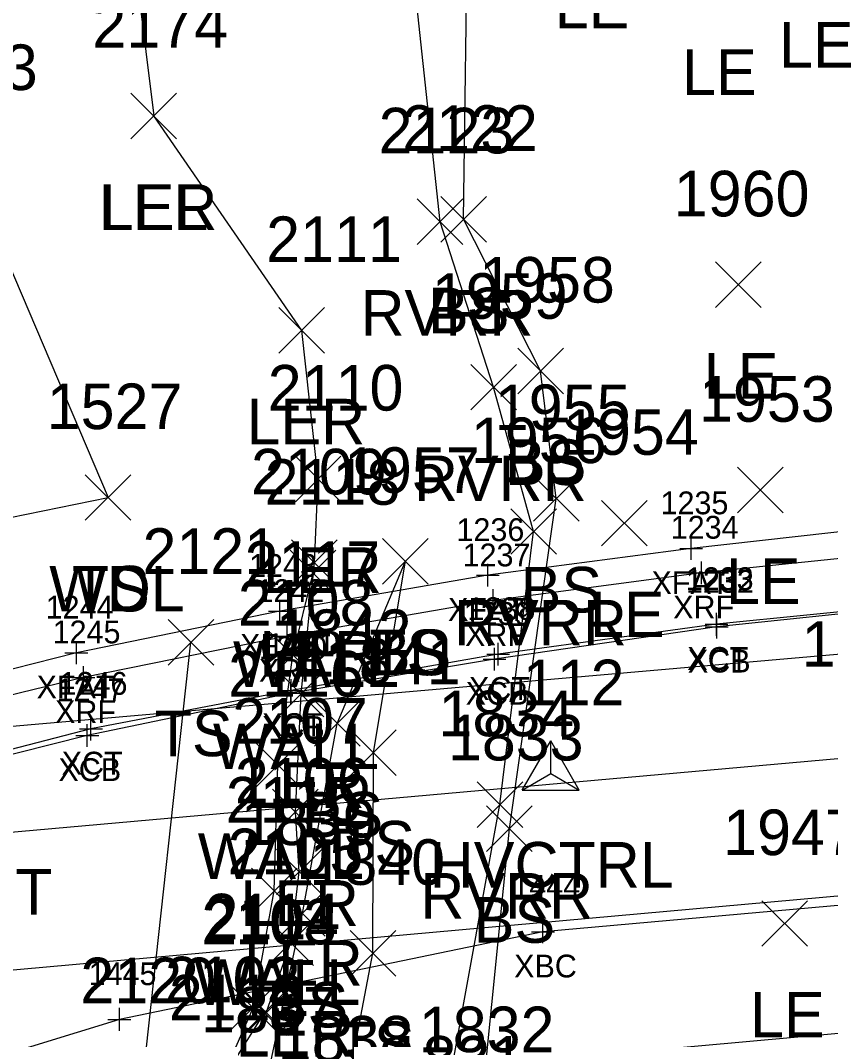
# Model space of a CAD drawing. Extents: x 1638344 to 1639591, y 610835 to 612202.
# Drawn here: x 1638651.32 to 1638686.84, y 611696.6 to 611741.32 of the extents above; entities that cross this region are included whole.
import ezdxf

# ---------------------------------------------------------------- set-up
doc = ezdxf.new("R2010")
doc.units = 0
for name, color, linetype in [('B_A', 7, 'Continuous'), ('B_I', 7, 'Continuous'), ('B_TIC', 7, 'Continuous'), ('BB', 7, 'Continuous'), ('BDC', 7, 'Continuous'), ('BELB', 7, 'Continuous'), ('BF', 7, 'Continuous'), ('BR', 7, 'Continuous'), ('C_A', 7, 'Continuous'), ('C_I', 7, 'Continuous'), ('CPSM', 7, 'Continuous'), ('L_A', 7, 'Continuous'), ('L_I', 7, 'Continuous'), ('L_TIC', 7, 'Continuous'), ('LARO', 7, 'Continuous'), ('LAWA', 7, 'Continuous'), ('LAWE', 7, 'Continuous'), ('LELB', 7, 'Continuous'), ('LW', 7, 'Continuous'), ('R_C', 7, 'Continuous')]:
    doc.layers.add(name, color=color, linetype=linetype)

msp = doc.modelspace()

# ---------------------------------------------------------------- linework, layer by layer
at = {"layer": 'B_TIC'}
for p, q in [((1638680.737, 611718.15), (1638680.813, 611718.15)), ((1638671.818, 611716.974), (1638671.893, 611716.974)), ((1638681.184, 611717.08), (1638681.26, 611717.08)), ((1638672.058, 611715.864), (1638672.133, 611715.864)), ((1638662.698, 611715.401), (1638662.773, 611715.401)), ((1638681.842, 611714.822), (1638681.918, 611714.822)), ((1638663.021, 611714.299), (1638663.096, 611714.299)), ((1638681.854, 611714.706), (1638681.93, 611714.706)), ((1638653.777, 611713.573), (1638653.853, 611713.573)), ((1638672.27, 611713.507), (1638672.345, 611713.507)), ((1638672.111, 611713.295), (1638672.187, 611713.295)), ((1638654.083, 611712.487), (1638654.159, 611712.487)), ((1638663.182, 611711.795), (1638663.257, 611711.795)), ((1638663.199, 611711.921), (1638663.275, 611711.921)), ((1638654.256, 611709.944), (1638654.331, 611709.944)), ((1638654.417, 611710.23), (1638654.493, 611710.23)), ((1638674.236, 611701.328), (1638674.312, 611701.328)), ((1638655.662, 611697.489), (1638655.737, 611697.489))]:
    msp.add_line(p, q, dxfattribs=at)
for points in [[(1638680.734, 611717.65), (1638680.734, 611718.65)], [(1638680.234, 611718.15), (1638681.234, 611718.15)], [(1638671.814, 611716.474), (1638671.814, 611717.474)], [(1638681.181, 611716.58), (1638681.181, 611717.58)], [(1638671.314, 611716.974), (1638672.314, 611716.974)], [(1638680.681, 611717.08), (1638681.681, 611717.08)], [(1638672.054, 611715.364), (1638672.054, 611716.364)], [(1638662.694, 611714.901), (1638662.694, 611715.901)], [(1638671.554, 611715.864), (1638672.554, 611715.864)], [(1638662.194, 611715.401), (1638663.194, 611715.401)], [(1638681.839, 611714.322), (1638681.839, 611715.322)], [(1638681.851, 611714.206), (1638681.851, 611715.206)], [(1638663.017, 611713.799), (1638663.017, 611714.799)], [(1638681.339, 611714.822), (1638682.339, 611714.822)], [(1638662.517, 611714.299), (1638663.517, 611714.299)], [(1638681.351, 611714.706), (1638682.351, 611714.706)], [(1638653.774, 611713.073), (1638653.774, 611714.073)], [(1638672.266, 611713.007), (1638672.266, 611714.007)], [(1638653.274, 611713.573), (1638654.274, 611713.573)], [(1638671.766, 611713.507), (1638672.766, 611713.507)], [(1638672.108, 611712.795), (1638672.108, 611713.795)], [(1638654.08, 611711.987), (1638654.08, 611712.987)], [(1638671.608, 611713.295), (1638672.608, 611713.295)], [(1638653.58, 611712.487), (1638654.58, 611712.487)], [(1638663.178, 611711.295), (1638663.178, 611712.295)], [(1638663.196, 611711.421), (1638663.196, 611712.421)], [(1638662.678, 611711.795), (1638663.678, 611711.795)], [(1638662.696, 611711.921), (1638663.696, 611711.921)], [(1638654.414, 611709.73), (1638654.414, 611710.73)], [(1638654.252, 611709.444), (1638654.252, 611710.444)], [(1638653.752, 611709.944), (1638654.752, 611709.944)], [(1638653.914, 611710.23), (1638654.914, 611710.23)], [(1638674.233, 611700.828), (1638674.233, 611701.828)], [(1638673.733, 611701.328), (1638674.733, 611701.328)], [(1638655.658, 611696.989), (1638655.658, 611697.989)], [(1638655.158, 611697.489), (1638656.158, 611697.489)]]:
    msp.add_lwpolyline(points, dxfattribs=at)
at = {"layer": 'BB'}
for points in [[(1638734.87, 611717.669), (1638645.425, 611709.859)], [(1638734.903, 611713.182), (1638645.469, 611705.203)], [(1638735.197, 611707.211), (1638645.609, 611699.159)], [(1638735.113, 611701.19), (1638645.728, 611693.119)]]:
    msp.add_lwpolyline(points, dxfattribs=at)
at = {"layer": 'BDC'}
for points in [[(1638737.305, 611718.795), (1638737.221, 611715.93), (1638737.034, 611715.608), (1638736.539, 611715.364), (1638735.749, 611715.325), (1638725.935, 611715.986), (1638717.241, 611716.45), (1638708.031, 611716.471), (1638699.246, 611716.24), (1638689.973, 611715.561), (1638681.851, 611714.706), (1638672.108, 611713.295), (1638663.178, 611711.795), (1638654.252, 611709.944), (1638645.027, 611707.62), (1638643.746, 611707.614), (1638643.485, 611708.194), (1638643.486, 611710.833)], [(1638737.078, 611718.736), (1638737.03, 611716.376), (1638736.823, 611715.856), (1638736.034, 611715.473), (1638725.908, 611716.152), (1638717.252, 611716.548), (1638708.082, 611716.671), (1638699.284, 611716.36), (1638690.06, 611715.643), (1638681.839, 611714.822), (1638672.266, 611713.507), (1638663.196, 611711.921), (1638654.414, 611710.23), (1638644.982, 611707.789), (1638643.919, 611707.854), (1638643.654, 611708.237), (1638643.636, 611710.999)]]:
    msp.add_lwpolyline(points, dxfattribs=at)
at = {"layer": 'BELB'}
msp.add_lwpolyline([(1638736.563, 611702.566), (1638717.385, 611703.723), (1638696.176, 611703.285), (1638674.233, 611701.328), (1638655.658, 611697.489), (1638644.13, 611693.949)], dxfattribs=at)
at = {"layer": 'BF'}
msp.add_lwpolyline([(1638737.078, 611718.736), (1638726.453, 611719.594), (1638717.231, 611720.061), (1638708.125, 611720.112), (1638698.897, 611719.862), (1638689.982, 611719.193), (1638680.734, 611718.15), (1638671.814, 611716.974), (1638662.694, 611715.401), (1638653.774, 611713.573), (1638643.636, 611710.999)], dxfattribs=at)
at = {"layer": 'BR'}
msp.add_lwpolyline([(1638736.42, 611718.625), (1638736.346, 611717.75), (1638726.195, 611718.354), (1638717.373, 611718.813), (1638708.189, 611718.979), (1638699.169, 611718.709), (1638690.094, 611717.999), (1638681.181, 611717.08), (1638672.054, 611715.864), (1638663.017, 611714.299), (1638654.08, 611712.487), (1638644.592, 611710.18), (1638644.314, 611711.068)], dxfattribs=at)
at = {"layer": 'CPSM'}
for p, q in [((1638673.324, 611707.548), (1638674.574, 611709.713)), ((1638675.824, 611707.548), (1638674.574, 611709.713)), ((1638674.575, 611708.27), (1638674.574, 611709.713)), ((1638673.324, 611707.548), (1638674.575, 611708.27)), ((1638674.575, 611708.27), (1638674.575, 611708.27)), ((1638674.575, 611708.27), (1638675.824, 611707.548)), ((1638673.324, 611707.548), (1638675.824, 611707.548))]:
    msp.add_line(p, q, dxfattribs=at)
at = {"layer": 'L_TIC'}
for points in [[(1638656.167, 611736.126), (1638658.167, 611738.126)], [(1638658.167, 611736.126), (1638656.167, 611738.126)], [(1638656.167, 611736.126), (1638658.167, 611738.126)], [(1638658.167, 611736.126), (1638656.167, 611738.126)], [(1638669.752, 611731.595), (1638671.752, 611733.595)], [(1638671.752, 611731.595), (1638669.752, 611733.595)], [(1638668.72, 611731.484), (1638670.72, 611733.484)], [(1638670.72, 611731.484), (1638668.72, 611733.484)], [(1638681.795, 611728.72), (1638683.795, 611730.72)], [(1638683.795, 611728.72), (1638681.795, 611730.72)], [(1638662.653, 611726.717), (1638664.653, 611728.717)], [(1638664.653, 611726.717), (1638662.653, 611728.717)], [(1638673.129, 611724.937), (1638675.129, 611726.937)], [(1638675.129, 611724.937), (1638673.129, 611726.937)], [(1638671.065, 611724.227), (1638673.065, 611726.227)], [(1638673.065, 611724.227), (1638671.065, 611726.227)], [(1638663.377, 611720.2), (1638665.377, 611722.2)], [(1638665.377, 611720.2), (1638663.377, 611722.2)], [(1638682.768, 611719.71), (1638684.768, 611721.71)], [(1638684.768, 611719.71), (1638682.768, 611721.71)], [(1638654.164, 611719.387), (1638656.164, 611721.387)], [(1638656.164, 611719.387), (1638654.164, 611721.387)], [(1638654.164, 611719.387), (1638656.164, 611721.387)], [(1638656.164, 611719.387), (1638654.164, 611721.387)], [(1638673.815, 611719.343), (1638675.815, 611721.343)], [(1638675.815, 611719.343), (1638673.815, 611721.343)], [(1638676.805, 611718.259), (1638678.805, 611720.259)], [(1638678.805, 611718.259), (1638676.805, 611720.259)], [(1638672.822, 611717.895), (1638674.822, 611719.895)], [(1638674.822, 611717.895), (1638672.822, 611719.895)], [(1638663.209, 611716.521), (1638665.209, 611718.521)], [(1638665.209, 611716.521), (1638663.209, 611718.521)], [(1638667.203, 611716.588), (1638669.203, 611718.588)], [(1638669.203, 611716.588), (1638667.203, 611718.588)], [(1638667.203, 611716.588), (1638669.203, 611718.588)], [(1638669.203, 611716.588), (1638667.203, 611718.588)], [(1638663.155, 611716.068), (1638665.155, 611718.068)], [(1638665.155, 611716.068), (1638663.155, 611718.068)], [(1638657.799, 611713.035), (1638659.799, 611715.035)], [(1638659.799, 611713.035), (1638657.799, 611715.035)], [(1638662.272, 611712.469), (1638664.272, 611714.469)], [(1638664.272, 611712.469), (1638662.272, 611714.469)], [(1638662.624, 611710.768), (1638664.624, 611712.768)], [(1638664.624, 611710.768), (1638662.624, 611712.768)], [(1638664.216, 611709.473), (1638666.216, 611711.473)], [(1638666.216, 611709.473), (1638664.216, 611711.473)], [(1638665.797, 611708.194), (1638667.797, 611710.194)], [(1638667.797, 611708.194), (1638665.797, 611710.194)], [(1638661.609, 611707.652), (1638663.609, 611709.652)], [(1638663.609, 611707.652), (1638661.609, 611709.652)], [(1638662.377, 611705.584), (1638664.377, 611707.584)], [(1638664.377, 611705.584), (1638662.377, 611707.584)], [(1638671.343, 611705.91), (1638673.343, 611707.91)], [(1638673.343, 611705.91), (1638671.343, 611707.91)], [(1638671.758, 611704.85), (1638673.758, 611706.85)], [(1638673.758, 611704.85), (1638671.758, 611706.85)], [(1638662.547, 611702.961), (1638664.547, 611704.961)], [(1638664.547, 611702.961), (1638662.547, 611704.961)], [(1638661.45, 611702.124), (1638663.45, 611704.124)], [(1638663.45, 611702.124), (1638661.45, 611704.124)], [(1638662.689, 611701.135), (1638664.689, 611703.135)], [(1638664.689, 611701.135), (1638662.689, 611703.135)], [(1638683.827, 611700.695), (1638685.827, 611702.695)], [(1638685.827, 611700.695), (1638683.827, 611702.695)], [(1638662.175, 611699.857), (1638664.175, 611701.857)], [(1638664.175, 611699.857), (1638662.175, 611701.857)], [(1638665.775, 611699.389), (1638667.775, 611701.389)], [(1638667.775, 611699.389), (1638665.775, 611701.389)], [(1638660.52, 611696.998), (1638662.52, 611698.998)], [(1638662.52, 611696.998), (1638660.52, 611698.998)], [(1638661.023, 611696.78), (1638663.023, 611698.78)], [(1638663.023, 611696.78), (1638661.023, 611698.78)], [(1638661.102, 611696.781), (1638663.102, 611698.781)], [(1638663.102, 611696.781), (1638661.102, 611698.781)]]:
    msp.add_lwpolyline(points, dxfattribs=at)
at = {"layer": 'LARO'}
for points in [[(1638668.019, 611809.745), (1638662.223, 611800.014), (1638655.604, 611791.826), (1638656.981, 611771.118), (1638658.475, 611759.642), (1638655.748, 611748.56), (1638657.167, 611737.126)], [(1638677.874, 611655.022), (1638679.486, 611663.994), (1638679.763, 611666.345), (1638666.378, 611670.719), (1638664.402, 611680.56), (1638659.089, 611680.603), (1638655.538, 611679.933), (1638651.379, 611684.077), (1638658.688, 611689.813), (1638660.426, 611695.236), (1638662.023, 611697.78), (1638662.102, 611697.781), (1638663.175, 611700.857), (1638663.547, 611703.961), (1638663.377, 611706.584), (1638663.624, 611711.768), (1638664.209, 611717.521), (1638664.377, 611721.2), (1638663.653, 611727.717), (1638657.167, 611737.126)]]:
    msp.add_lwpolyline(points, dxfattribs=at)
at = {"layer": 'LAWA'}
msp.add_lwpolyline([(1638628.579, 611823.011), (1638631.205, 611793.982), (1638636.051, 611775.752), (1638635.636, 611758.892), (1638640.82, 611743.59), (1638643.87, 611738.789), (1638644.553, 611728.051), (1638647.989, 611718.924), (1638655.164, 611720.387)], dxfattribs=at)
at = {"layer": 'LAWE'}
msp.add_lwpolyline([(1638639.67, 611638.455), (1638651.909, 611645.684), (1638665.496, 611649.056), (1638676.655, 611655.904), (1638679.763, 611666.345), (1638680.738, 611673.208), (1638671.065, 611682.751), (1638669.589, 611691.757), (1638672.343, 611706.91), (1638673.822, 611718.895), (1638672.065, 611725.227), (1638669.72, 611732.484), (1638668.237, 611746.392), (1638671.195, 611757.256), (1638673.317, 611772.941), (1638670.756, 611783.04), (1638669.117, 611796.001), (1638668.019, 611809.745), (1638668.561, 611829.322)], dxfattribs=at)
at = {"layer": 'LELB'}
for points in [[(1638679.486, 611663.994), (1638681.736, 611674.726), (1638674.098, 611683.416), (1638671.48, 611693.048), (1638672.758, 611705.85), (1638674.815, 611720.343), (1638674.129, 611725.937), (1638670.752, 611732.595), (1638670.942, 611746.441), (1638675.273, 611751.303), (1638676.509, 611756.644), (1638676.731, 611772.908), (1638673.469, 611784.839), (1638671, 611795.643), (1638672.782, 611808.122), (1638670.59, 611829.25)], [(1638643.87, 611738.789), (1638648.823, 611735.263), (1638655.164, 611720.387)], [(1638665.17, 611684.637), (1638658.464, 611683.85), (1638661.932, 611693.915), (1638663.689, 611702.135), (1638665.216, 611710.473), (1638668.203, 611717.588)], [(1638665.17, 611684.637), (1638665.296, 611692.638), (1638666.775, 611700.389), (1638666.797, 611709.194), (1638668.203, 611717.588)], [(1638653.675, 611690.062), (1638656.73, 611695.195), (1638658.799, 611714.035)]]:
    msp.add_lwpolyline(points, dxfattribs=at)
at = {"layer": 'LW'}
msp.add_lwpolyline([(1638658.718, 611691.07), (1638659.956, 611694.444), (1638661.52, 611697.998), (1638662.45, 611703.124), (1638662.609, 611708.652), (1638663.272, 611713.469), (1638664.155, 611717.068)], dxfattribs=at)

# ---------------------------------------------------------------- texts
at = {"layer": 'B_A'}
for s, p in [('XFAT', (1638678.99, 611716.15)), ('XRF', (1638679.941, 611715.08)), ('XFAT', (1638670.07, 611714.974)), ('XRF', (1638670.814, 611713.864)), ('XFAT', (1638660.95, 611713.401)), ('XCT', (1638680.559, 611712.822)), ('XCB', (1638680.587, 611712.706)), ('XRF', (1638661.777, 611712.299)), ('XFAT', (1638652.03, 611711.573)), ('XCT', (1638670.987, 611711.507)), ('XCB', (1638670.844, 611711.295)), ('XRF', (1638652.84, 611710.487)), ('XCB', (1638661.915, 611709.795)), ('XCT', (1638661.916, 611709.921)), ('XCB', (1638652.988, 611707.944)), ('XCT', (1638653.134, 611708.23)), ('XBC', (1638672.969, 611699.328))]:
    msp.add_text(s, height=1, dxfattribs=at).set_placement(p)
at = {"layer": 'B_I'}
for s, p in [('1235', (1638679.388, 611719.65)), ('1236', (1638670.44, 611718.474)), ('1234', (1638679.834, 611718.58)), ('1237', (1638670.708, 611717.364)), ('1243', (1638661.348, 611716.901)), ('1233', (1638680.492, 611716.322)), ('1232', (1638680.504, 611716.206)), ('1242', (1638661.671, 611715.799)), ('1244', (1638652.427, 611715.073)), ('1239', (1638670.758, 611714.795)), ('1238', (1638670.92, 611715.007)), ('1245', (1638652.733, 611713.987)), ('1240', (1638661.789, 611713.295)), ('1241', (1638662.133, 611713.421)), ('1246', (1638653.04, 611711.73)), ('1247', (1638652.906, 611711.444)), ('1444', (1638672.886, 611702.828)), ('1445', (1638654.312, 611698.989))]:
    msp.add_text(s, height=1, dxfattribs=at).set_placement(p)
at = {"layer": 'C_A'}
msp.add_text('HVCTRL', height=2, dxfattribs=at).set_placement((1638669.268, 611703.27))
at = {"layer": 'C_I'}
msp.add_text('112', height=2, dxfattribs=at).set_placement((1638673.346, 611711.27))
at = {"layer": 'L_A'}
for s, p in [('LE', (1638674.751, 611740.967)), ('LE', (1638684.579, 611739.247)), ('LE', (1638680.332, 611738.045)), ('LER', (1638654.75, 611732.126)), ('LEL', (1638654.805, 611732.126)), ('RVRR', (1638666.232, 611727.484)), ('BS', (1638669.192, 611727.595)), ('LE', (1638681.283, 611724.72)), ('LER', (1638661.236, 611722.717)), ('BS', (1638672.57, 611720.937)), ('RVRR', (1638668.577, 611720.227)), ('LER', (1638661.96, 611716.2)), ('TS', (1638653.574, 611715.387)), ('LE', (1638682.256, 611715.71)), ('WDL', (1638652.582, 611715.387)), ('BS', (1638673.256, 611715.343)), ('LE', (1638676.293, 611714.259)), ('RVRR', (1638670.334, 611713.895)), ('LER', (1638661.792, 611712.521)), ('TS', (1638666.613, 611712.588)), ('BS', (1638666.644, 611712.588)), ('WALL', (1638660.643, 611712.068)), ('TS', (1638657.209, 611709.035)), ('WALL', (1638659.76, 611708.469)), ('LER', (1638661.207, 611706.768)), ('BS', (1638663.657, 611705.473)), ('TS', (1638665.206, 611704.194)), ('WALL', (1638659.097, 611703.652)), ('LER', (1638660.96, 611701.584)), ('RVRR', (1638668.855, 611701.91)), ('BS', (1638671.199, 611700.85)), ('LER', (1638661.13, 611698.961)), ('WALL', (1638658.938, 611698.124)), ('BS', (1638662.13, 611697.135)), ('LE', (1638683.315, 611696.695)), ('LER', (1638660.758, 611695.857)), ('TS', (1638665.184, 611695.389))]:
    msp.add_text(s, height=2, dxfattribs=at).set_placement(p)
at = {"layer": 'L_I'}
for s, p in [('2174', (1638654.474, 611740.126)), ('2174', (1638654.474, 611740.126)), ('1523', (1638646.13, 611738.263)), ('2122', (1638668.059, 611735.595)), ('2123', (1638667.027, 611735.484)), ('1960', (1638679.968, 611732.72)), ('2111', (1638662.094, 611730.717)), ('1958', (1638671.436, 611728.937)), ('1959', (1638669.365, 611728.227)), ('2110', (1638662.165, 611724.2)), ('1953', (1638681.075, 611723.71)), ('1527', (1638652.471, 611723.387)), ('1527', (1638652.471, 611723.387)), ('1955', (1638672.122, 611723.343)), ('1954', (1638675.112, 611722.259)), ('1956', (1638671.074, 611721.895)), ('2109', (1638661.43, 611720.521)), ('1957', (1638665.51, 611720.588)), ('1957', (1638665.51, 611720.588)), ('2118', (1638662.029, 611720.068)), ('2121', (1638656.673, 611717.035)), ('2117', (1638661.146, 611716.469)), ('2108', (1638660.853, 611714.768)), ('1842', (1638662.523, 611713.473)), ('1948', (1638685.571, 611712.958)), ('1841', (1638664.671, 611712.194)), ('2116', (1638660.427, 611711.652)), ('2107', (1638660.606, 611709.584)), ('1834', (1638669.65, 611709.91)), ('1833', (1638670.065, 611708.85)), ('2106', (1638660.721, 611706.961)), ('2115', (1638660.324, 611706.124)), ('1839', (1638660.988, 611705.135)), ('1947', (1638682.134, 611704.695)), ('2105', (1638660.404, 611703.857)), ('1840', (1638663.995, 611703.389)), ('2103', (1638659.252, 611700.78)), ('2104', (1638659.331, 611700.781)), ('2114', (1638659.394, 611700.998)), ('2120', (1638653.95, 611698.195)), ('2102', (1638657.654, 611698.236)), ('2113', (1638657.83, 611697.444)), ('1837', (1638659.239, 611696.915)), ('1832', (1638668.787, 611696.048)), ('1838', (1638662.603, 611695.638)), ('1831', (1638667.464, 611694.757))]:
    msp.add_text(s, height=2, dxfattribs=at).set_placement(p)
at = {"layer": 'R_C'}
msp.add_text('SGR STEEL POST', height=2, dxfattribs=at).set_placement((1638629.689, 611702.084))

doc.saveas('drawing.dxf')
